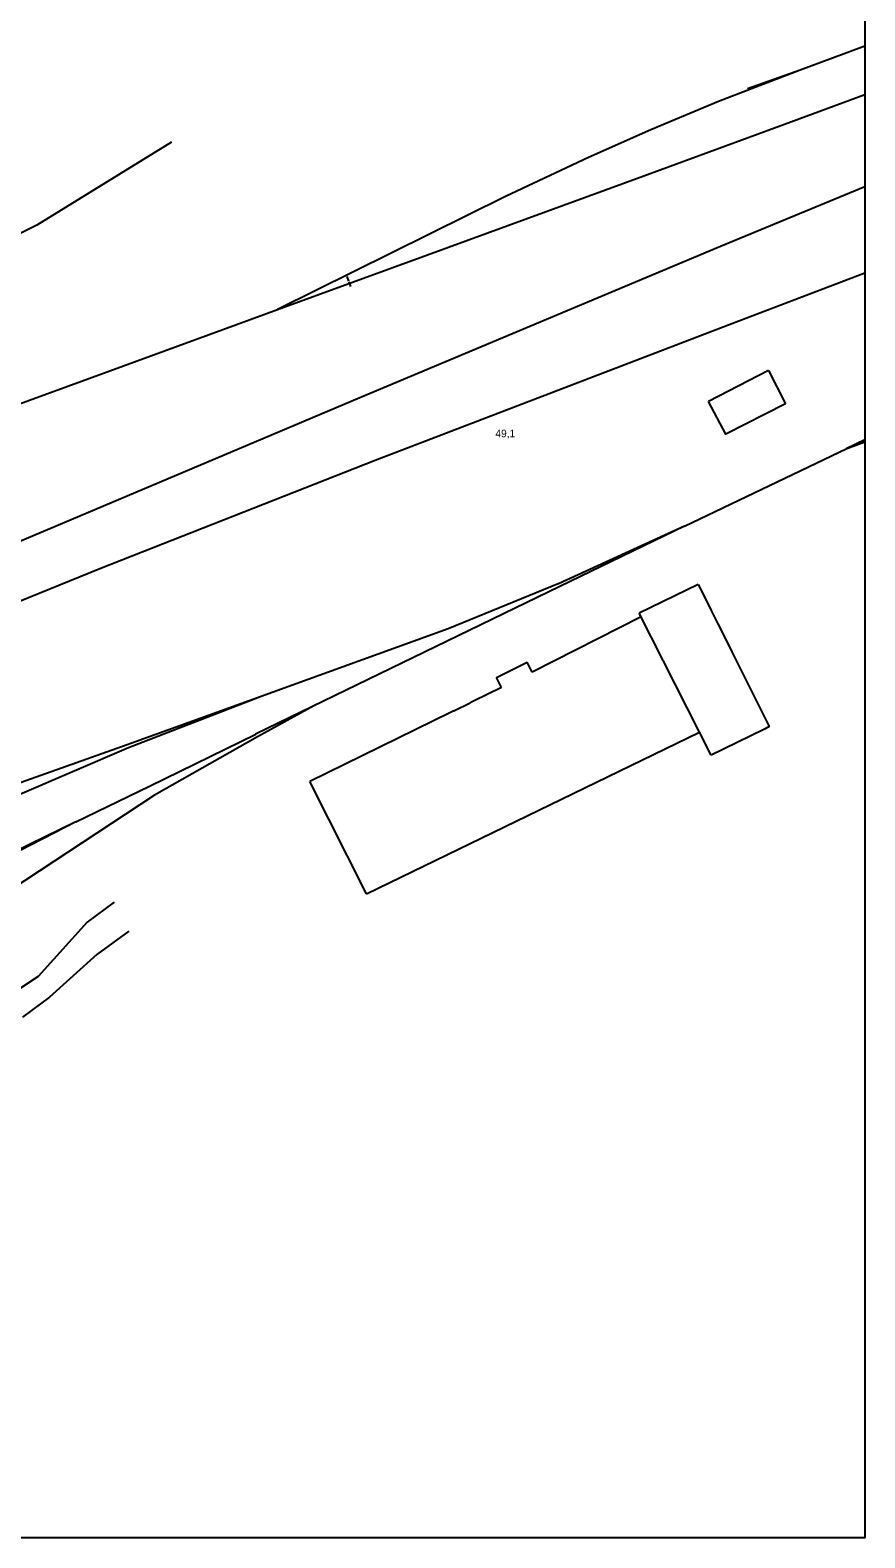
# Model space of a CAD drawing. Extents: x -932734 to -932083, y -737151 to -736752.
# Drawn here: x -932473.97 to -932465.77, y -736822.8 to -736807.96 of the extents above; entities that cross this region are included whole.
import ezdxf

# ---------------------------------------------------------------- set-up
doc = ezdxf.new("R2010")
doc.units = 0
for name, color, linetype in [('Objekty_stávající', 7, 'Continuous'), ('SL_24_VODOVOD_PITNA', 7, 'Continuous'), ('WA_34_SCHODISTE', 7, 'Continuous'), ('WA_40_APARATY', 7, 'Continuous'), ('WA_46_TEXT', 7, 'Continuous')]:
    doc.layers.add(name, color=color, linetype=linetype)

# ---------------------------------------------------------------- blocks, each defined once
blk = doc.blocks.new('5.121_1')
blk.add_line((0, 0), (0, 0.0005))
blk = doc.blocks.new('přehledka_1')
at = {"layer": 'Objekty_stávající'}
for p, q in [((0.098646, -0.03634), (0.097605, -0.036709)), ((0.096368, -0.045312), (0.099561, -0.043783)), ((0.099551, -0.043788), (0.099915, -0.043611))]:
    blk.add_line(p, q, dxfattribs=at)
for points in [[(0.099915, -0.035871), (0.098646, -0.03634), (0.097038, -0.03696), (0.09571, -0.037516), (0.09448, -0.03806), (0.092852, -0.038824), (0.088366, -0.04105)], [(0.070214, -0.047688), (0.073116, -0.046624), (0.075926, -0.045598), (0.079086, -0.044442), (0.082654, -0.043138), (0.085068, -0.04226), (0.088366, -0.04105), (0.091314, -0.039974), (0.09557, -0.038422), (0.09846, -0.037358), (0.099915, -0.036822)], [(0.034457, -0.065218), (0.036094, -0.06463), (0.042022, -0.062434), (0.046232, -0.060838), (0.053854, -0.05786), (0.057568, -0.05638), (0.066464, -0.052712), (0.072204, -0.050292), (0.078868, -0.04748), (0.08431, -0.045184), (0.089984, -0.04278), (0.097074, -0.039804), (0.099915, -0.038627)], [(0.03708, -0.065218), (0.04231, -0.06328), (0.04657, -0.061666), (0.054136, -0.05872), (0.066806, -0.053566), (0.072606, -0.051164), (0.079336, -0.048394), (0.084902, -0.046136), (0.090286, -0.044012), (0.0973, -0.041326), (0.099915, -0.040329)], [(0.09956, -0.043784), (0.099915, -0.043657)], [(0.096369, -0.045311), (0.09392, -0.046503), (0.087936, -0.049405)], [(0.096368, -0.045311), (0.093888, -0.046448)], [(0.093882, -0.046451), (0.091721, -0.04733), (0.087973, -0.048691)], [(0.087976, -0.04869), (0.085436, -0.049675), (0.0833, -0.050595), (0.07568, -0.054149), (0.069227, -0.057414)], [(0.089083, -0.048849), (0.087974, -0.049455), (0.085947, -0.050608), (0.079133, -0.055094)], [(0.087973, -0.048691), (0.08541, -0.049617), (0.081712, -0.050929)], [(0.084401, -0.051131), (0.085851, -0.050427), (0.087937, -0.049405)], [(0.084401, -0.051131), (0.081958, -0.052321), (0.078416, -0.054033), (0.075967, -0.055229), (0.070542, -0.057871), (0.065749, -0.060528), (0.059036, -0.065218)], [(0.084401, -0.051131), (0.08199, -0.052367), (0.07512, -0.056635), (0.0672, -0.061933)]]:
    blk.add_lwpolyline(points, dxfattribs=at)
at = {"layer": 'WA_34_SCHODISTE'}
blk.add_lwpolyline([(0, 0), (0.099915, 0), (0.099915, -0.065218), (0, -0.065218)], close=True, dxfattribs=at)
at = {"layer": 'WA_40_APARATY'}
for p, q in [((0.098023, -0.042251), (0.09684, -0.042858)), ((0.098023, -0.042251), (0.098358, -0.042904)), ((0.095514, -0.047099), (0.093372, -0.048183)), ((0.093372, -0.048183), (0.093278, -0.04799)), ((0.092768, -0.048489), (0.09267, -0.048288)), ((0.090116, -0.052546), (0.096662, -0.049367))]:
    blk.add_line(p, q, dxfattribs=at)
for points in [[(0.098358, -0.042904), (0.097184, -0.043506), (0.09684, -0.042858)], [(0.09664, -0.04646), (0.095478, -0.047028)], [(0.09664, -0.04646), (0.096742, -0.046665), (0.096896, -0.046974), (0.097026, -0.047235), (0.09718, -0.047545), (0.0973, -0.047785), (0.09745, -0.048087), (0.098034, -0.049258), (0.097953, -0.049298), (0.097644, -0.049451), (0.097431, -0.049556), (0.097124, -0.049707), (0.096892, -0.049822)], [(0.096892, -0.049822), (0.095478, -0.047028)], [(0.09267, -0.048288), (0.093278, -0.04799)], [(0.092768, -0.048489), (0.09222, -0.048757), (0.092157, -0.048788)], [(0.091835, -0.048945), (0.091767, -0.048978), (0.088998, -0.050334)], [(0.091835, -0.048945), (0.092157, -0.048788)], [(0.090116, -0.052546), (0.088998, -0.050334)]]:
    blk.add_lwpolyline(points, dxfattribs=at)
at = {"layer": 'WA_46_TEXT'}
for points in [[(0.086278, -0.037758), (0.083634, -0.039394), (0.082248, -0.040084), (0.081559, -0.040377), (0.07832, -0.04125), (0.0753, -0.042404), (0.07175, -0.043768), (0.067214, -0.04551), (0.06388, -0.04677), (0.063028, -0.047065), (0.06121, -0.047734), (0.056748, -0.049352), (0.052088, -0.051014), (0.049772, -0.051898), (0.048486, -0.05233), (0.047346, -0.0527), (0.043028, -0.054132), (0.038862, -0.05539), (0.036736, -0.05607), (0.036645, -0.056105)], [(0.085156, -0.05271), (0.08462, -0.053106), (0.08366, -0.054176), (0.080928, -0.055976)], [(0.085442, -0.053284), (0.08481, -0.053742), (0.083884, -0.054582), (0.083348, -0.054974)]]:
    blk.add_lwpolyline(points, dxfattribs=at)
at = {"layer": 'Objekty_stávající', "xscale": 0.2, "yscale": 0.20000000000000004, "rotation": 19.393445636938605}
for p in [(0.08977, -0.040493), (0.089808, -0.040599)]:
    blk.add_blockref('5.121_1', p, dxfattribs=at)
at = {"layer": 'Objekty_stávající'}
blk.add_text('49,1', height=0.00015, dxfattribs=at).set_placement((0.09265, -0.043564))

msp = doc.modelspace()

# ---------------------------------------------------------------- block references
at = {"layer": 'SL_24_VODOVOD_PITNA', "xscale": 499.99957, "yscale": 499.99957}
msp.add_blockref('přehledka_1', (-932515.723, -736790.187), dxfattribs=at)

doc.saveas('drawing.dxf')
